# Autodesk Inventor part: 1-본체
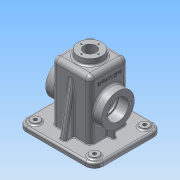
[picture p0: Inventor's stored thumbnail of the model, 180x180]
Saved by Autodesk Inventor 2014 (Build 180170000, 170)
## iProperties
Created: 2015-12
Part Number: 1-본체
Material: 알루미늄 6061
Document SubType Name: Modeling
Designer: Administrator
Density: 2.71 g/cm^3
Appearance: 알루미늄 - 평지
Mass: 770.297 g
Surface Area: 920.863 cm^2
Volume: 284.243 cm^3
Author: Administrator
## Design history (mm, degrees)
sketch "스케치1"
  geometry: L1 (65, -57.5)-(-65, -57.5); L2 (-65, -57.5)-(-65, 57.5); L3 (-65, 57.5)-(65, 57.5); L4 (65, 57.5)-(65, -57.5); L5 (65, -57.5)-(-65, 57.5); L6 (-65, -57.5)-(65, 57.5); 1 further point
  constraints: 12 end point, 2 midpoint, 2 parallel, 1 horizontal, 1 perpendicular
  dimensions: "d0" = 130 distance of L2.end L3.end; "d1" = 115 distance of L1.end L2.end
extrude "돌출1" new body sketch "스케치1" distance "d2" = 8; taper "d3" = 0 deg
node "작업 평면1"
sketch "스케치2"
  geometry: L1 (32.5, -32.5)-(-32.5, -32.5); L2 (-32.5, -32.5)-(-32.5, 32.5); L3 (-32.5, 32.5)-(32.5, 32.5); L4 (32.5, 32.5)-(32.5, -32.5); L5 (32.5, -32.5)-(-32.5, 32.5); L6 (-32.5, -32.5)-(32.5, 32.5); 1 further point
  constraints: 12 end point, 2 midpoint, 2 parallel, 1 horizontal, 1 perpendicular
  dimensions: "d5" = 65 distance of L2.end L3.end; "d6" = 65 distance of L1.end L2.end
extrude "돌출2" join sketch "스케치2" distance "d7" = 108; taper "d8" = 0 deg
fillet "모깎기1" dims "d9" = 15
sketch "스케치3"
  geometry: C1 r 7.5 at (-50, 42.5); A1 r 15 centre (-50, 42.5) between (-50, 57.5) and (-65, 42.5) reference; 1 further point
  constraints: 1 centre point, 1 coincident
  dimensions: "d10" = 15 diameter of C1
extrude "돌출3" join sketch "스케치3" distance "d11" = 3; taper "d12" = 0 deg
sketch "스케치4"
  geometry: C1 r 7.5 at (0, 0) reference; C2 r 3 at (0, 0); 1 further point
  constraints: 1 centre point, 1 coincident
  dimensions: "d13" = 6 diameter of C2
extrude "돌출4" cut sketch "스케치4" distance "d14" = 22; taper "d15" = 0 deg
feature "쉘1" dims "d23" = 8, "d24" = 5
sketch "스케치5"
  geometry: L1 (50, 57.5)-(-50, 57.5) reference; L2 (-65, 42.5)-(-65, -42.5) reference; L3 (-50, -57.5)-(50, -57.5) reference; L4 (65, -42.5)-(65, 42.5) reference; L5 (-50, 52.5)-(50, 52.5); L6 (60, 42.5)-(60, -42.5); L7 (50, -52.5)-(-50, -52.5); L8 (-60, -42.5)-(-60, 42.5); A1 r 15 centre (50, 42.5) between (65, 42.5) and (50, 57.5) reference; A2 r 15 centre (-50, 42.5) between (-50, 57.5) and (-65, 42.5) reference; A3 r 15 centre (-50, -42.5) between (-65, -42.5) and (-50, -57.5) reference; A4 r 15 centre (50, -42.5) between (50, -57.5) and (65, -42.5) reference; A5 r 10 centre (50, 42.5) between (60, 42.5) and (50, 52.5); A6 r 10 centre (50, -42.5) between (50, -52.5) and (60, -42.5); A7 r 10 centre (-50, -42.5) between (-60, -42.5) and (-50, -52.5); A8 r 10 centre (-50, 42.5) between (-50, 52.5) and (-60, 42.5); 1 further point
  constraints: 8 end point, 8 point on circle, 4 centre point, 7 other
  dimensions: "d16" = 5 distance between parallel lines of L1 L5
sketch "스케치6"
  geometry: L1 (-8, -10)-(-8, 75) reference; C1 r 27.5 at (45, 32.5); 2 further points
  constraints: 1 centre point, 1 horizontal alignment
  dimensions: "d19" = 55 diameter of C1; "d97" = 53 distance from line of L1 C1.centre
extrude "돌출6" join sketch "스케치6" distance "d21" = 15; taper "d22" = 0 deg
sketch "스케치7"
  geometry: C1 r 27.5 at (0, 0) reference; C2 r 17.5 at (0, 0); 1 further point
  constraints: 1 centre point, 1 coincident
  dimensions: "d25" = 35 diameter of C2
extrude "돌출7" cut sketch "스케치7" distance "d26" = 17; taper "d27" = 0 deg
sketch "스케치8"
  geometry: C1 r 17.5 at (0, 0) reference; C2 r 15 at (0, 0); 1 further point
  constraints: 1 centre point, 1 coincident
  dimensions: "d28" = 30 diameter of C2
extrude "돌출8" cut sketch "스케치8" distance "d29" = 3; taper "d30" = 0 deg
sketch "스케치9" dims "d31" = 42
  geometry: C1 r 17.5 at (0, 0) reference; C2 r 27.5 at (0, 0) reference; 3 further points
  constraints: 2 horizontal alignment, 1 coincident, 2 other
hole "구멍1" sketch "스케치9" at (21, 0) diameter "d32" = 3.242; stored, may be unused: countersink angle "d36" = 90 deg, drill point angle "d38" = 118 deg; dims "d33" = 8, "d34" = 4, "d35" = 2, "d37" = 10
fillet "모깎기2" dims "d42" = 8
fillet "모깎기3" dims "d43" = 8
node "작업 평면2"
sketch "스케치10"
  geometry: C1 r 20 at (0, 0); 1 further point
  constraints: 1 centre point, 1 coincident
  dimensions: "d46" = 40 diameter of C1
extrude "돌출9" join sketch "스케치10" stored distance "d47" = 3; taper "d48" = 5 deg
sketch "스케치11"
  geometry: C1 r 20 at (0, 0) reference; C2 r 10.5 at (0, 0)
  constraints: 1 centre point, 1 coincident
  dimensions: "d49" = 21 diameter of C2
extrude "돌출10" cut sketch "스케치11" distance "d50" = 45.25; taper "d51" = 0 deg
sketch "스케치12" dims "d52" = 29
  geometry: C1 r 10.5 at (0, 0) reference; C2 r 20 at (0, 0) reference; 2 further points
  constraints: 2 horizontal alignment, 1 coincident, 2 other
hole "구멍2" sketch "스케치12" at (-14.5, 0) diameter "d53" = 2.459; stored, may be unused: countersink angle "d57" = 90 deg, drill point angle "d59" = 118 deg; dims "d54" = 7, "d55" = 4, "d56" = 2, "d58" = 9
node "작업 평면3"
sketch "스케치13"
  geometry: L1 (-30.808, 102.662)-(-30.808, 8); L2 (-57.5, 0)-(-57.5, 8) reference; L3 (-30.808, 8)-(-47.5, 8); L4 (-47.5, 8)-(-30.808, 102.662); L5 (-57.5, 8)-(-42.5, 8) reference; 2 further points
  constraints: 6 end point, 1 collinear, 1 parallel, 1 perpendicular
  dimensions: "d65" = 10 distance from line of L2 L3.end; "d66" = 10 deg angle of L2 L4; "d67" = 94.66241 distance of L1.start L1.end
extrude "돌출11" join sketch "스케치13" stored distance "d68" = 10; taper "d69" = 0 deg
fillet "모깎기5" dims "d70" = 3
fillet "모깎기6" dims "d71" = 3
fillet "모깎기9" dims "d74" = 3
fillet "모깎기10" dims "d75" = 0.3
sketch "스케치14"
  geometry: L1 (32.5, 24.5)-(32.5, -24.5) reference; L2 (5, 44.454)-(5, 35.5) reference; L3 (32.5, 3)-(42.5, 3); L4 (42.5, 3)-(42.5, -3); L5 (42.5, -3)-(32.5, -3); L6 (32.5, -3)-(32.5, 3); L7 (27.5, -27.5)-(27.5, 27.5) reference; 4 further points
  constraints: 8 end point, 2 perpendicular, 2 point on line, 1 collinear, 1 horizontal alignment, 1 midpoint, 1 parallel
  dimensions: "d79" = 6 distance of L3.end L4.end; "d84" = 15 distance between parallel lines of L7 L4
extrude "돌출12" join sketch "스케치14" stored distance "d81" = 10; taper "d82" = 0 deg
fillet "모깎기14" dims "d83" = 3
fillet "모깎기15" dims "d85" = 3
fillet "모깎기16" dims "d86" = 1
sketch "스케치15"
  geometry: L1 (0, -8)-(91, -8) reference; L2 (-18, 4.5)-(-18, 44.5) reference; 2 further points
  constraints: 1 other
  dimensions: "d87" = 32.5 distance from line of L1 point (8, 24.5); "d88" = 26 distance from line of L2 point (8, 24.5)
feature "엠보싱1" sketch "스케치15" dims "d89" = 0.5, "d90" = 0
extrude "돌출13" join sketch "스케치5" distance "d91" = 2; taper "d92" = 0 deg
sketch "스케치16"
  geometry: C1 r 3 at (-50, 42.5); C2 r 3 at (-50, -42.5); C3 r 3 at (50, -42.5); C4 r 3 at (50, 42.5); A1 r 10 centre (-50, 42.5) between (-50, 52.5) and (-60, 42.5) reference; A2 r 10 centre (-50, -42.5) between (-60, -42.5) and (-50, -52.5) reference; A3 r 10 centre (50, -42.5) between (50, -52.5) and (60, -42.5) reference; A4 r 10 centre (50, 42.5) between (60, 42.5) and (50, 52.5) reference; 1 further point
  constraints: 4 centre point, 4 coincident, 3 equal radius
  dimensions: "d93" = 6 diameter of C1
extrude "돌출14" cut sketch "스케치16" distance "d94" = 40; taper "d95" = 0 deg
fillet "모깎기17" dims "d96" = 3
sketch "스케치17"
  geometry: L1 (27.5, -27.5)-(-27.5, -27.5); L2 (-27.5, -27.5)-(-27.5, 27.5); L3 (-27.5, 27.5)-(27.5, 27.5); L4 (27.5, 27.5)-(27.5, -27.5); L5 (27.5, -27.5)-(-27.5, 27.5); L6 (-27.5, -27.5)-(27.5, 27.5); 1 further point
  constraints: 12 end point, 2 midpoint, 2 parallel, 1 horizontal, 1 perpendicular
  dimensions: "d98" = 55 distance of L2.end L3.end; "d99" = 55 distance of L1.end L2.end
extrude "돌출15" cut sketch "스케치17" distance "d100" = 105; taper "d101" = 0 deg
fillet "모깎기18" dims "d102" = 3
fillet "모깎기19" dims "d103" = 3
node "솔리드1"
mirror "대칭1"
mirror "대칭2"
pattern_circular "원형 패턴1" dims angle "d40" = 360 deg
mirror "대칭3"
pattern_circular "원형 패턴2" dims angle "d61" = 360 deg
mirror "대칭4"
mirror "대칭5"
other parameters: "d4" = 0, "d63" = 0
